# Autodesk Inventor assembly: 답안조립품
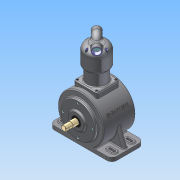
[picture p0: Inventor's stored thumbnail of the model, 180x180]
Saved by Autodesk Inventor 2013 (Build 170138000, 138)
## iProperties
Created: 2015-06
Part Number: 답안조립품
Document SubType Name: Assembly
Designer: ST4
Author: ST4
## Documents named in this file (15)
- C:\Users\ST4\Desktop\450605V1011\답안조립품.iam
- C:\Users\ST4\Desktop\450605V1011\본체.ipt
- C:\Users\ST4\Desktop\450605V1011\베어링 6204.ipt
- C:\Users\ST4\Desktop\450605V1011\크랭크 서브축.ipt
- C:\Users\ST4\Desktop\450605V1011\메인 크랭크 축-구동부.ipt
- C:\Users\ST4\Desktop\450605V1011\커넥팅 로드.ipt
- C:\Users\ST4\Desktop\450605V1011\베어링 NA 4902.ipt
- C:\Users\ST4\Desktop\450605V1011\메인커버.ipt
- C:\Users\ST4\Desktop\450605V1011\오일실.ipt
- C:\Users\ST4\Desktop\450605V1011\피스톤.ipt
- C:\Users\ST4\Desktop\450605V1011\피스톤 핀.ipt
- C:\Users\ST4\Desktop\450605V1011\실린더.ipt
- C:\Users\ST4\Desktop\450605V1011\실린더헤드.ipt
- C:\Users\ST4\Desktop\450605V1011\M5x0.8.ipt
- C:\Users\ST4\Desktop\450605V1011\M4x0.7.ipt
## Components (10 placed, 4 different names)
1. 피스톤:1
2. 피스톤 핀:1
3. M4x0.7:1
4. M4x0.7:2
5. M4x0.7:3
6. M4x0.7:4
7. M5x0.8:1
8. M5x0.8:2
9. M5x0.8:3
10. M5x0.8:4
